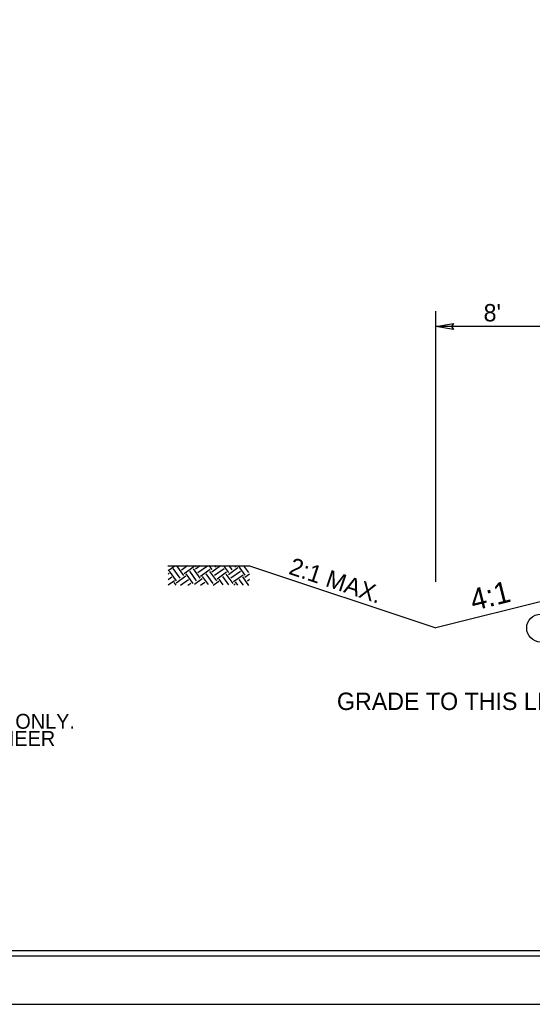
# Model space of a CAD drawing. Extents: x 3025871 to 3026431, y 707165 to 707825.
# Drawn here: x 3026107.4 to 3026143.1, y 707397.1 to 707465.6 of the extents above; entities that cross this region are included whole.
import ezdxf

# ---------------------------------------------------------------- set-up
doc = ezdxf.new("R2010")
doc.units = 0
for name, color, linetype in [('Old_Level_39', 7, 'Continuous'), ('Prop Drainage Structure Junction Box with Slab Lid TB 840 34 CELL', 7, 'Continuous'), ('Sheet Cutting Line CELL', 7, 'Continuous'), ('Typical Grade Point Symbol CELL', 7, 'Continuous'), ('Typical Terminator CELL', 7, 'Continuous'), ('Typical Text Centerline CELL', 7, 'Continuous'), ('Typical Text General CELL', 7, 'Continuous'), ('Typical Text Grade Point CELL', 7, 'Continuous')]:
    doc.layers.add(name, color=color, linetype=linetype)

msp = doc.modelspace()

# ---------------------------------------------------------------- linework, layer by layer
at = {"layer": 'Old_Level_39'}
msp.add_lwpolyline([(3026273.948, 707558.686), (3026023.973, 707558.686), (3026023.973, 707400.421), (3026273.948, 707400.421)], close=True, dxfattribs=at)
at = {"layer": 'Prop Drainage Structure Junction Box with Slab Lid TB 840 34 CELL'}
for p, q in [((3026136.416, 707426.489), (3026136.416, 707445.341)), ((3026148.416, 707444.268), (3026136.416, 707444.268))]:
    msp.add_line(p, q, dxfattribs=at)
at = {"layer": 'Sheet Cutting Line CELL'}
msp.add_lwpolyline([(3026272.073, 707558.304), (3026047.073, 707558.304), (3026047.073, 707400.804), (3026272.073, 707400.804)], close=True, dxfattribs=at)
at = {"layer": 'Typical Grade Point Symbol CELL'}
msp.add_circle((3026143.707, 707423.263), 0.972, dxfattribs=at)
at = {"layer": 'Typical Terminator CELL'}
msp.add_lwpolyline([(3026274.623, 707562.054), (3026022.023, 707562.054), (3026022.023, 707397.054), (3026274.623, 707397.054)], close=True, dxfattribs=at)
at = {"layer": 'Typical Text Centerline CELL'}
msp.add_lwpolyline([(3026137.641, 707444.057), (3026136.416, 707444.268), (3026137.647, 707444.485), (3026137.491, 707444.268)], close=True, dxfattribs=at)
at = {"layer": 'Typical Text Grade Point CELL'}
for p, q in [((3026117.731, 707427.609), (3026123.416, 707427.609)), ((3026117.731, 707427.609), (3026123.416, 707427.609)), ((3026117.753, 707427.28), (3026118.213, 707427.61)), ((3026117.753, 707427.28), (3026118.213, 707427.61)), ((3026118.592, 707426.743), (3026118.112, 707427.411)), ((3026118.592, 707426.743), (3026118.112, 707427.411)), ((3026118.843, 707426.923), (3026118.363, 707427.591)), ((3026118.843, 707426.923), (3026118.363, 707427.591)), ((3026118.506, 707427.568), (3026118.567, 707427.611)), ((3026118.506, 707427.568), (3026118.567, 707427.611)), ((3026118.686, 707427.317), (3026119.098, 707427.613)), ((3026118.686, 707427.317), (3026119.098, 707427.613)), ((3026118.866, 707427.066), (3026119.535, 707427.547)), ((3026118.866, 707427.066), (3026119.535, 707427.547)), ((3026119.992, 707426.735), (3026119.511, 707427.403)), ((3026119.992, 707426.735), (3026119.511, 707427.403)), ((3026119.678, 707427.523), (3026119.613, 707427.614)), ((3026119.678, 707427.523), (3026119.613, 707427.614)), ((3026119.655, 707427.38), (3026119.983, 707427.615)), ((3026119.655, 707427.38), (3026119.983, 707427.615)), ((3026119.835, 707427.129), (3026120.503, 707427.609)), ((3026119.835, 707427.129), (3026120.503, 707427.609)), ((3026120.827, 707427.335), (3026120.625, 707427.617)), ((3026120.827, 707427.335), (3026120.625, 707427.617)), ((3026120.804, 707427.192), (3026121.399, 707427.619)), ((3026120.804, 707427.192), (3026121.399, 707427.619)), ((3026120.984, 707426.941), (3026121.652, 707427.421)), ((3026120.984, 707426.941), (3026121.652, 707427.421)), ((3026121.078, 707427.515), (3026121.004, 707427.618)), ((3026121.078, 707427.515), (3026121.004, 707427.618)), ((3026121.976, 707427.147), (3026121.644, 707427.609)), ((3026121.976, 707427.147), (3026121.644, 707427.609)), ((3026121.952, 707427.003), (3026122.621, 707427.484)), ((3026121.952, 707427.003), (3026122.621, 707427.484)), ((3026122.227, 707427.327), (3026122.015, 707427.621)), ((3026122.227, 707427.327), (3026122.015, 707427.621)), ((3026122.477, 707427.507), (3026122.404, 707427.609)), ((3026122.477, 707427.507), (3026122.404, 707427.609)), ((3026123.125, 707426.959), (3026122.658, 707427.609)), ((3026123.125, 707426.959), (3026122.658, 707427.609)), ((3026123.375, 707427.139), (3026123.038, 707427.609)), ((3026123.375, 707427.139), (3026123.038, 707427.609)), ((3026123.416, 707427.609), (3026136.416, 707423.276)), ((3026117.753, 707427.026), (3026117.838, 707427.087)), ((3026117.753, 707427.026), (3026117.838, 707427.087)), ((3026117.753, 707426.646), (3026118.018, 707426.837)), ((3026117.753, 707426.646), (3026118.018, 707426.837)), ((3026118.342, 707426.563), (3026117.861, 707427.231)), ((3026118.342, 707426.563), (3026117.861, 707427.231)), ((3026118.318, 707426.419), (3026118.987, 707426.899)), ((3026118.318, 707426.419), (3026118.987, 707426.899)), ((3026119.49, 707426.374), (3026119.01, 707427.043)), ((3026119.49, 707426.374), (3026119.01, 707427.043)), ((3026119.741, 707426.555), (3026119.261, 707427.223)), ((3026119.741, 707426.555), (3026119.261, 707427.223)), ((3026119.586, 707426.317), (3026120.135, 707426.711)), ((3026119.586, 707426.317), (3026120.135, 707426.711)), ((3026120.015, 707426.878), (3026120.684, 707427.359)), ((3026120.015, 707426.878), (3026120.684, 707427.359)), ((3026120.559, 707426.297), (3026120.159, 707426.855)), ((3026120.559, 707426.297), (3026120.159, 707426.855)), ((3026120.89, 707426.367), (3026120.409, 707427.035)), ((3026120.89, 707426.367), (3026120.409, 707427.035)), ((3026121.14, 707426.547), (3026120.66, 707427.215)), ((3026121.14, 707426.547), (3026120.66, 707427.215)), ((3026121.164, 707426.69), (3026121.832, 707427.171)), ((3026121.164, 707426.69), (3026121.832, 707427.171)), ((3026121.974, 707426.269), (3026121.558, 707426.847)), ((3026121.974, 707426.269), (3026121.558, 707426.847)), ((3026122.289, 707426.359), (3026121.809, 707427.027)), ((3026122.289, 707426.359), (3026121.809, 707427.027)), ((3026122.133, 707426.753), (3026122.801, 707427.233)), ((3026122.133, 707426.753), (3026122.801, 707427.233)), ((3026122.313, 707426.502), (3026122.981, 707426.983)), ((3026122.313, 707426.502), (3026122.981, 707426.983)), ((3026123.388, 707426.24), (3026122.958, 707426.839)), ((3026123.388, 707426.24), (3026122.958, 707426.839)), ((3026123.101, 707426.815), (3026123.416, 707427.041)), ((3026123.101, 707426.815), (3026123.416, 707427.041)), ((3026117.753, 707426.266), (3026118.198, 707426.586)), ((3026117.753, 707426.266), (3026118.198, 707426.586)), ((3026118.314, 707426.249), (3026118.175, 707426.442)), ((3026118.314, 707426.249), (3026118.175, 707426.442)), ((3026118.61, 707426.249), (3026119.167, 707426.649)), ((3026118.61, 707426.249), (3026119.167, 707426.649)), ((3026119.139, 707426.249), (3026119.347, 707426.398)), ((3026119.139, 707426.249), (3026119.347, 707426.398)), ((3026120.021, 707426.249), (3026120.315, 707426.461)), ((3026120.021, 707426.249), (3026120.315, 707426.461)), ((3026120.902, 707426.249), (3026121.284, 707426.523)), ((3026120.902, 707426.249), (3026121.284, 707426.523)), ((3026121.588, 707426.277), (3026121.308, 707426.667)), ((3026121.588, 707426.277), (3026121.308, 707426.667)), ((3026122.331, 707426.262), (3026122.433, 707426.335)), ((3026122.331, 707426.262), (3026122.433, 707426.335)), ((3026122.616, 707426.256), (3026122.456, 707426.479)), ((3026122.616, 707426.256), (3026122.456, 707426.479)), ((3026123.002, 707426.248), (3026122.707, 707426.659)), ((3026123.002, 707426.248), (3026122.707, 707426.659)), ((3026123.281, 707426.565), (3026123.416, 707426.661)), ((3026123.281, 707426.565), (3026123.416, 707426.661)), ((3026144.416, 707425.276), (3026136.416, 707423.276))]:
    msp.add_line(p, q, dxfattribs=at)

# ---------------------------------------------------------------- texts
at = {"layer": 'Prop Drainage Structure Junction Box with Slab Lid TB 840 34 CELL'}
for s, height, p in [("8'", 1.2089, (3026139.734, 707444.629)), ('GRADE TO THIS LINE', 1.20892, (3026129.516, 707417.558))]:
    msp.add_text(s, height=height, dxfattribs=at).set_placement(p)
at = {"layer": 'Typical Text General CELL'}
for s, p in [('STATION RANGES ARE APPROXIMATE ONLY.', (3026080.876, 707416.25)), ('GRADE MAY BE ADJUSTED BY ENGINEER', (3026081.807, 707415.056))]:
    msp.add_text(s, height=1.03533, rotation=0.00189, dxfattribs=at).set_placement(p)
at = {"layer": 'Typical Text Grade Point CELL'}
for s, height, rotation, p in [('2:1 MAX.', 1.2089, 341.56505, (3026126.083, 707427.055)), ('4:1', 1.5, 14.03624, (3026139.016, 707424.456))]:
    msp.add_text(s, height=height, rotation=rotation, dxfattribs=at).set_placement(p)

doc.saveas('drawing.dxf')
